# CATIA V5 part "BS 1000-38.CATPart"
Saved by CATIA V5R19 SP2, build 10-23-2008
Part number: BS 1000-38
Bounding box of the stored display mesh (mm): x -24.865 to 24.865, y -24.997 to 24.997, z 0 to 114
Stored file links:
  C:\Users\Bora\Desktop\3D Katı model\BS serisi\BS 1000\BS 1000-38.CATPart
  C:\Program Files\Dassault Systemes\B19\intel_a\reffiles\standard\MetricThinPitch.txt
  C:\Program Files\Dassault Systemes\B19\intel_a\reffiles\standard\MetricThickPitch.txt
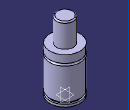
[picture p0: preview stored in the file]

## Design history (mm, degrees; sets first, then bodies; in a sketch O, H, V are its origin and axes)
Body1 (main body)
  Sketch1 on yz-plane, origin (0, 0, 0), H (0, 1, 0), V (0, 0, 1)
    point P2 (14, 112)
    line L1 (14, 112) -> (14, 75)
    point P3 (25, 62.5)
    line L2 (25, 75) -> (25, 62.5)
    point P6 (25, 58.5)
    line L3 (25, 58.5) -> (25, 7.5)
    line L4 (25, 4) -> (25, 0)
    point P9 (25, 58.5)
    point P10 (25, 62.5)
    arc A1 centre (25, 60.5) radius 2 from (25, 62.5) to (25, 58.5) ccw
    point P12 (14, 112)
    arc A2 centre (12, 112) radius 2 from (14, 112) to (12, 114) ccw
    point P13 (22.5, 4)
    point P14 (22.5, 4)
    line L5 (22.5, 7.5) -> (22.5, 4)
    line L6 (12, 114) -> (0, 114)
    line L7 (14, 75) -> (25, 75)
    line L8 (0, 0) -> (25, 0)
    line L9 (22.5, 7.5) -> (25, 7.5)
    line L10 (22.5, 4) -> (25, 4)
    tangency: L6 A2
    horizontal: L7 H, L8 H, L9 H, L10 H
    coincidence: P2 P12, P3 P10, P6 P9, P13 P14
  Shaft1: profile Sketch1, axis Sketch1.V, angle 360
  Sketch2 on face of Shaft1 from Sketch1.L8, origin (0, 0, 0), H (1, 0, 0), V (0, -1, 0)
    point P1 (10, 0)
    distance P1 V = 10
  Hole1: placed by Sketch2, at (10, 0, 0) direction (0, 0, 1), diameter 6.647, depth 6, threaded "M8", thread diameter 8, thread depth 6, pitch 1.25
  CircPattern1: of Hole1, instances 2, angular step 180, axis from xy-plane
